(* Logix 5000 project; controller AMCI_5034_PTO_AM_Sample vendor 1 type 14 code 190 rev 37.11; software revision 37.00 *)

TASK MainTask (continuous, watchdog 500 ms) : MainProgram

MODULES
   Local : vendor 1 type 14 code 190 (5069 0, rev 37.11)
      AENTR : vendor 1 type 12 code 334 (Ethernet 192.168.1.40, rev 1.1)
         AMCI_5034_PTO_AM : vendor 10 type 100 code 34 (5034 1, rev 1.1, StandardDataDriven RPI 10 ms)
END_MODULES

TYPE AMCI_5034_PTO_AM_Input_Data :
STRUCT
   ConnectionFaulted : DINT;
   MovingCW : BOOL;
   MovingCCW : BOOL;
   InHoldState : BOOL;
   Stopped : BOOL;
   AtHome : BOOL;
   Accelerating : BOOL;
   Decelerating : BOOL;
   MoveComplete : BOOL;
   HomeInvalid : BOOL;
   InvalidProfile : BOOL;
   PositionInvalid : BOOL;
   InputError : BOOL;
   CommandError : BOOL;
   ConfigurationError : BOOL;
   ModuleOK : BOOL;
   GeneralPurposeOutputStatus : BOOL;
   Input1Active : BOOL;
   Input2Active : BOOL;
   Input3Active : BOOL;
   Input4Active : BOOL;
   bit_20_reserved : BOOL;
   bit_21_reserved : BOOL;
   bit_22_reserved : BOOL;
   EncoderFollowerMode : BOOL;
   BlendMoveRunning : BOOL;
   BlendMoveAcknowledge : BOOL;
   MinimumRegistrationProgrammed : BOOL;
   EncoderMotionDirection : BOOL;
   MultipleInputsWithSameFunction : BOOL;
   FSCExceedsNumberOfDataBits : BOOL;
   AbsoluteEncoderSetupError : BOOL;
   bit_31_reserved : BOOL;
   CurrentPosition : DINT;
   EncoderPosition : DINT;
   CapturedPosition : DINT;
END_STRUCT
END_TYPE

TYPE AMCI_5034_PTO_AM_Output_Data :
STRUCT
   Command_Word : DINT;
   TargetPosition : DINT;
   TargetVelocity : UDINT;
   Acceleration : DINT;
   Deceleration : DINT;
END_STRUCT
END_TYPE

ADD_ON_INSTRUCTION AMCI_5034_PTO_AM_Encoder_Follower   (* revision 1.0, vendor AMCI, ExecuteEnableInFalse *)
// AMCI Encoder Follower
// Revision note:
// 10/01/2025  Initial release of AOI.
// Help:
// AXIS INPUT DATA:  Input data from the AMCI 5034-PTO-AM.   Uses the AMCI_5034_PTO_Input_Data User Defined Data Type.
// AXIS OUTPUT DATA; Output data from the AOI to the AMCI 5034-PTO-AM.    Uses the AMCI_5034_PTO_Output_Data User Defined Data Type.
// DIRECTION_0_POSITIVECW_1_NEGATIVECCW: 0 to have the output steps be in the same direction as the encoder pulses.   1 to have the output steps be in the opposite direction from the encoder pulses.
// MULTIPLIER: The incoming encoder data is muliplied by this number.
// DIVISOR: The incomming encoder data is divided by this number.
// ACCELERATION: Acceleration Rate in units of steps / sec / ms.  Can be zero with the encoder follower.
// DECELERATION:  Deceleration Rate in units of steps / sec / ms.  Can be zero with the encoder follower.
// EN (Enable) Set when rung is true, Reset when rung is false
// DN (Done) Set when command is sent to the motion device.  Reset when the rung is false.
// ER (Error) Set when a command or input error failed to clear.  Reset when the rung is false.
// IP (In Process) Set when motion is occurring.   Reset when motion stops or the rung goes false.
VAR_IN_OUT
   Axis_Input_Data : AMCI_5034_PTO_AM_Input_Data; {required}
   Axis_Output_Data : AMCI_5034_PTO_AM_Output_Data; {required}
END_VAR
VAR_INPUT
   Direction_0_PositiveCW_1_NegativeCCW : BOOL; {required}
   Multiplier : DINT; {required}
   Divisor : DINT; {required}
   Acceleration : DINT; {required}
   Deceleration : DINT; {required}
END_VAR
VAR_OUTPUT
   EN : BOOL; {visible}   // set when rung with AOI is true
   DN : BOOL; {access Read Only, visible}   // set when move was succesfully initiated
   ER : BOOL; {visible}
   IP : BOOL; {visible}   // set when motion occurring
END_VAR
VAR
   command_data_block : DINT[5];
        [0]   // Command Word
        [1]   // Target Positon
        [2]   // Programmed Speed
        [3]   // Acceleration
        [4]   // Deceleration
   motion_occurring : BOOL; {access None}
   Internal_Enable : BOOL; {access None}   // set when driver ready to receive motion command
END_VAR

ROUTINE EnableInFalse   (* ladder *)
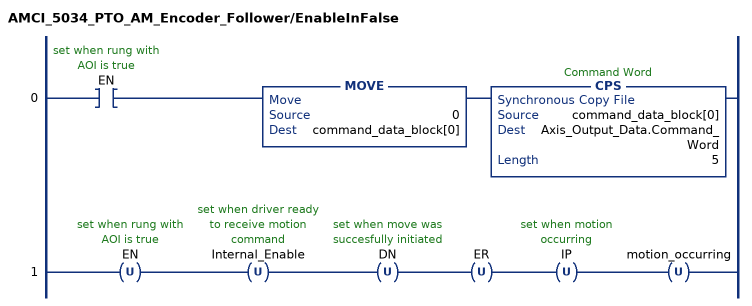
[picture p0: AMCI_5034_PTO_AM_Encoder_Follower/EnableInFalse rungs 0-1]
   0: XIC(EN)MOVE(0,command_data_block[0])CPS(command_data_block[0],Axis_Output_Data.Command_Word,5);
   1: OTU(EN)OTU(Internal_Enable)OTU(DN)OTU(ER)OTU(IP)OTU(motion_occurring);
END_ROUTINE

ROUTINE Logic   (* ladder *)
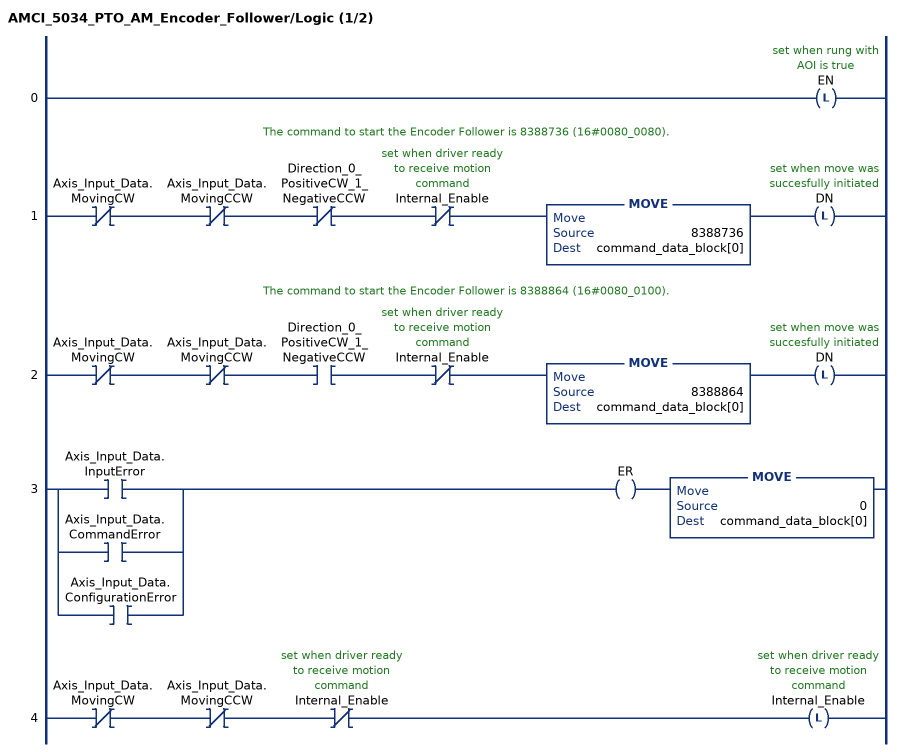
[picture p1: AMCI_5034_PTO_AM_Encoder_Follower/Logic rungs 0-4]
   0: OTL(EN);
   // The command to start the Encoder Follower is 8388736 (16#0080_0080).
   1: XIO(Axis_Input_Data.MovingCW)XIO(Axis_Input_Data.MovingCCW)XIO(Direction_0_PositiveCW_1_NegativeCCW)XIO(Internal_Enable)MOVE(8388736,command_data_block[0])OTL(DN);
   // The command to start the Encoder Follower is 8388864 (16#0080_0100).
   2: XIO(Axis_Input_Data.MovingCW)XIO(Axis_Input_Data.MovingCCW)XIC(Direction_0_PositiveCW_1_NegativeCCW)XIO(Internal_Enable)MOVE(8388864,command_data_block[0])OTL(DN);
   3: [XIC(Axis_Input_Data.InputError) ,XIC(Axis_Input_Data.CommandError) ,XIC(Axis_Input_Data.ConfigurationError) ]OTE(ER)MOVE(0,command_data_block[0]);
   4: XIO(Axis_Input_Data.MovingCW)XIO(Axis_Input_Data.MovingCCW)XIO(Internal_Enable)OTL(Internal_Enable);
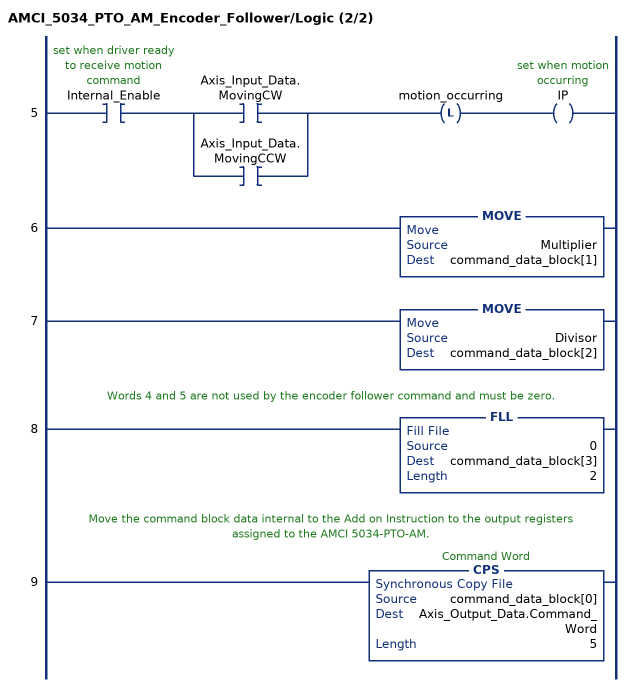
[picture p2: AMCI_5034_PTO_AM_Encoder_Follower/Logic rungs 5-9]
   5: XIC(Internal_Enable)[XIC(Axis_Input_Data.MovingCW) ,XIC(Axis_Input_Data.MovingCCW) ]OTL(motion_occurring)OTE(IP);
   6: MOVE(Multiplier,command_data_block[1]);
   7: MOVE(Divisor,command_data_block[2]);
   // Words 4 and 5 are not used by the encoder follower command and must be zero.
   8: FLL(0,command_data_block[3],2);
   // Move the command block data internal to the Add on Instruction to the output registers assigned to the AMCI 5034-PTO-AM.
   9: CPS(command_data_block[0],Axis_Output_Data.Command_Word,5);
END_ROUTINE
END_ADD_ON_INSTRUCTION

ADD_ON_INSTRUCTION AMCI_5034_PTO_AM_Hold   (* revision 1.0, vendor AMCI, ExecuteEnableInFalse *)
// AMCI Hold
// Revision note:
// 10/01/2025 Initial Release
// Help:
// AXIS INPUT DATA:  Input data from the AMCI 5034-PTO-AM.   Uses the AMCI_5034_PTO_Input_Data User Defined Data Type.
// AXIS OUTPUT DATA; Output data from the AOI to the AMCI 5034-PTO-AM.    Uses the AMCI_5034_PTO_Output_Data User Defined Data Type.
// EN (Enable) Set when rung is true, Reset when rung is false
// DN (Done) Set when command is sent to the motion device.  Reset when the rung is false.
// ER (Error) Set when a command or input error failed to clear.  Reset when the rung is false.
VAR_IN_OUT
   Axis_Input_Data : AMCI_5034_PTO_AM_Input_Data; {required}
   Axis_Output_Data : AMCI_5034_PTO_AM_Output_Data; {required}
END_VAR
VAR_OUTPUT
   EN : BOOL; {visible}   // set when rung with AOI is true
   DN : BOOL; {access Read Only, visible}   // set when reset error command sent to motion axis
   ER : BOOL; {access Read Only, visible}   // set when reset error command did not clear the error
END_VAR
VAR
   command_data_block : DINT[5];
        [0]   // Command Bits MSW
        [1]   // Command Bits LSW
        [2]   // Upper Target Position
        [3]   // Lower Target Position
        [4]   // Upper Programmed Speed
END_VAR

ROUTINE EnableInFalse   (* ladder *)
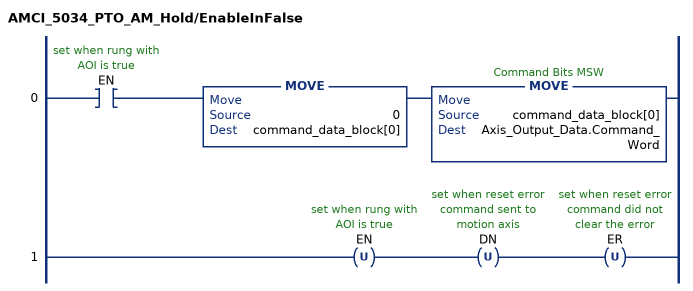
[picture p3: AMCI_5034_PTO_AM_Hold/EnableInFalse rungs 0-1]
   0: XIC(EN)MOVE(0,command_data_block[0])MOVE(command_data_block[0],Axis_Output_Data.Command_Word);
   1: OTU(EN)OTU(DN)OTU(ER);
END_ROUTINE

ROUTINE Logic   (* ladder *)
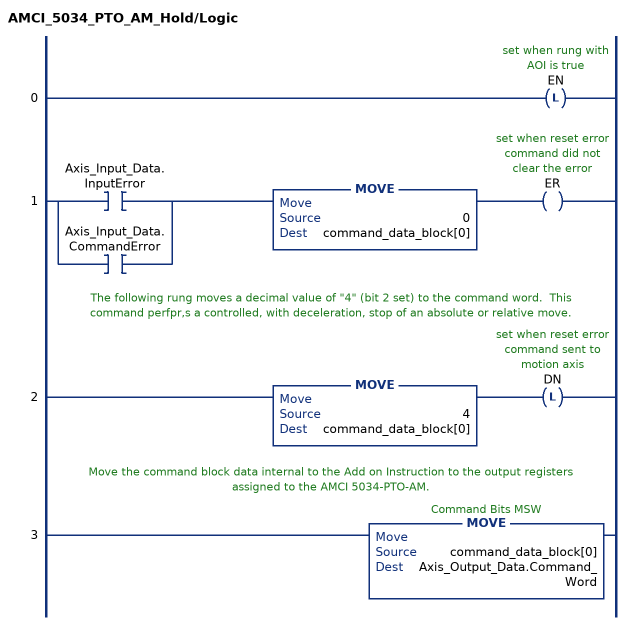
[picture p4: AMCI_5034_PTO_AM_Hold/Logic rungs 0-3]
   0: OTL(EN);
   1: [XIC(Axis_Input_Data.InputError) ,XIC(Axis_Input_Data.CommandError) ]MOVE(0,command_data_block[0])OTE(ER);
   // The following rung moves a decimal value of "4" (bit 2 set) to the command word.  This command perfpr,s a controlled, with deceleration, stop of an absolute or relative move.
   2: MOVE(4,command_data_block[0])OTL(DN);
   // Move the command block data internal to the Add on Instruction to the output registers assigned to the AMCI 5034-PTO-AM.
   3: MOVE(command_data_block[0],Axis_Output_Data.Command_Word);
END_ROUTINE
END_ADD_ON_INSTRUCTION

ADD_ON_INSTRUCTION AMCI_5034_PTO_AM_Immediate_Stop   (* revision 1.0, vendor AMCI, ExecuteEnableInFalse *)
// AMCI Immediate Stop
// Revision note:
// 10/01/2025 Initial Release
// Help:
// AXIS INPUT DATA:  Input data from the AMCI 5034-PTO-AM.   Uses the AMCI_5034_PTO_Input_Data User Defined Data Type.
// AXIS OUTPUT DATA; Output data from the AOI to the AMCI 5034-PTO-AM.    Uses the AMCI_5034_PTO_Output_Data User Defined Data Type.
// EN (Enable) Set when rung is true, Reset when rung is false
// DN (Done) Set when command is sent to the motion device.  Reset when the rung is false.
// ER (Error) Set when a command or input error failed to clear.  Reset when the rung is false.
VAR_IN_OUT
   Axis_Input_Data : AMCI_5034_PTO_AM_Input_Data; {required}
   Axis_Output_Data : AMCI_5034_PTO_AM_Output_Data; {required}
END_VAR
VAR_OUTPUT
   EN : BOOL; {visible}   // set when rung with AOI is true
   DN : BOOL; {access Read Only, visible}   // set when reset error command sent to motion axis
   ER : BOOL; {access Read Only, visible}   // set when reset error command did not clear the error
END_VAR
VAR
   command_data_block : DINT[5];
        [0]   // Command Bits MSW
        [1]   // Command Bits LSW
        [2]   // Upper Target Position
        [3]   // Lower Target Position
        [4]   // Upper Programmed Speed
END_VAR

ROUTINE EnableInFalse   (* ladder *)
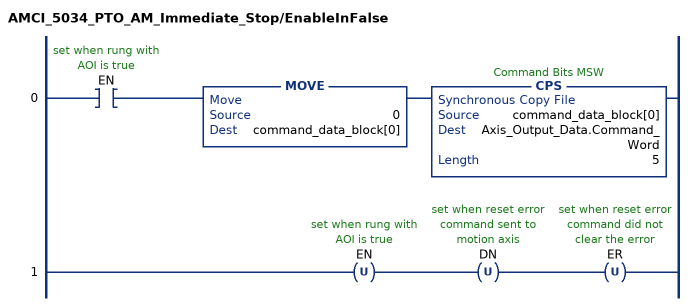
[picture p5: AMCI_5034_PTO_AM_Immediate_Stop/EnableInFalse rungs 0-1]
   0: XIC(EN)MOVE(0,command_data_block[0])CPS(command_data_block[0],Axis_Output_Data.Command_Word,5);
   1: OTU(EN)OTU(DN)OTU(ER);
END_ROUTINE

ROUTINE Logic   (* ladder *)
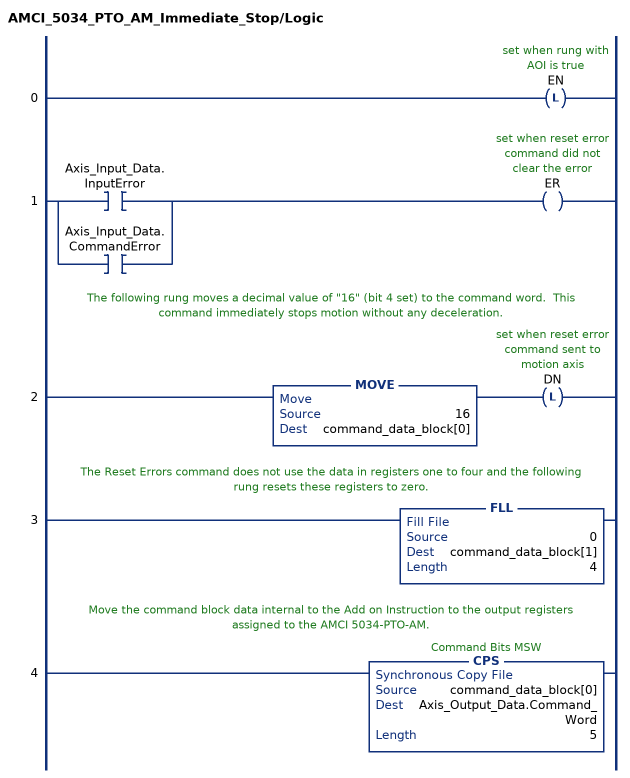
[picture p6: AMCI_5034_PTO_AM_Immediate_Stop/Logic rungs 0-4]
   0: OTL(EN);
   1: [XIC(Axis_Input_Data.InputError) ,XIC(Axis_Input_Data.CommandError) ]OTE(ER);
   // The following rung moves a decimal value of "16" (bit 4 set) to the command word.  This command immediately stops motion without any deceleration.
   2: MOVE(16,command_data_block[0])OTL(DN);
   // The Reset Errors command does not use the data in registers one to four and the following rung resets these registers to zero.
   3: FLL(0,command_data_block[1],4);
   // Move the command block data internal to the Add on Instruction to the output registers assigned to the AMCI 5034-PTO-AM.
   4: CPS(command_data_block[0],Axis_Output_Data.Command_Word,5);
END_ROUTINE
END_ADD_ON_INSTRUCTION

ADD_ON_INSTRUCTION AMCI_5034_PTO_AM_MAFR   (* revision 1.0, vendor AMCI, ExecuteEnableInFalse *)
// AMCI Reset Errors
// Revision note:
// 10/01/2025 Initial Release
// Help:
// MOTION AXIS FAULT RESET:   Resets Command and Input Errors.  It will also reset the Move Complete Status Bit.
// AXIS INPUT DATA:  Input data from the AMCI 5034-PTO-AM.   Uses the AMCI_5034_PTO_Input_Data User Defined Data Type.
// AXIS OUTPUT DATA; Output data from the AOI to the AMCI 5034-PTO-AM.    Uses the AMCI_5034_PTO_Output_Data User Defined Data Type.
// EN (Enable) Set when rung is true, Reset when rung is false
// DN (Done) Set when command is sent to the motion device.  Reset when the rung is false.
// ER (Error) Set when a command or input error failed to clear.  Reset when the rung is false.
VAR_IN_OUT
   Axis_Input_Data : AMCI_5034_PTO_AM_Input_Data; {required}
   Axis_Output_Data : AMCI_5034_PTO_AM_Output_Data; {required}
END_VAR
VAR_OUTPUT
   EN : BOOL; {visible}   // set when rung with AOI is true
   DN : BOOL; {access Read Only, visible}   // set when reset error command sent to motion axis
   ER : BOOL; {access Read Only, visible}   // set when reset error command did not clear the error
END_VAR
VAR
   command_data_block : DINT[5];
        [0]   // Command Bits MSW
        [1]   // Command Bits LSW
        [2]   // Upper Target Position
        [3]   // Lower Target Position
        [4]   // Upper Programmed Speed
END_VAR

ROUTINE EnableInFalse   (* ladder *)
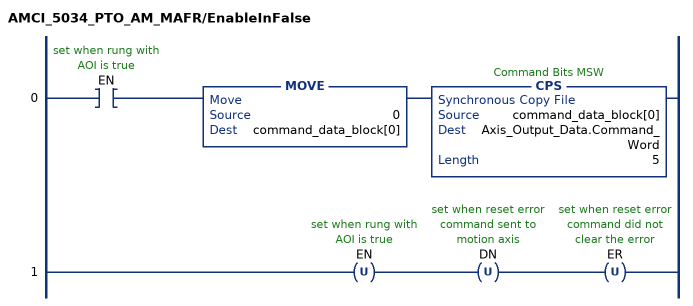
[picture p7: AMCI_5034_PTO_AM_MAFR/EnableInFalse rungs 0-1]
   0: XIC(EN)MOVE(0,command_data_block[0])CPS(command_data_block[0],Axis_Output_Data.Command_Word,5);
   1: OTU(EN)OTU(DN)OTU(ER);
END_ROUTINE

ROUTINE Logic   (* ladder *)
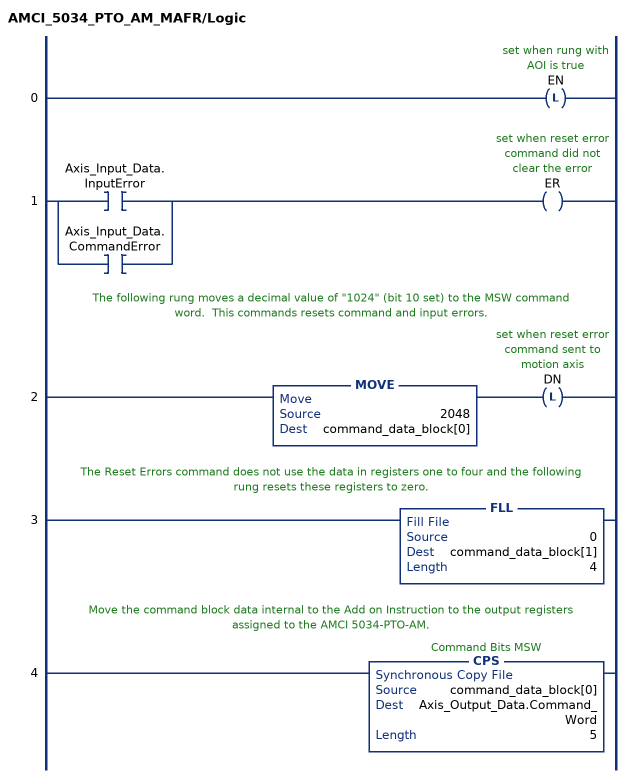
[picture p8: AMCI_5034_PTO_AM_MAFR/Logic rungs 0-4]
   0: OTL(EN);
   1: [XIC(Axis_Input_Data.InputError) ,XIC(Axis_Input_Data.CommandError) ]OTE(ER);
   // The following rung moves a decimal value of "1024" (bit 10 set) to the MSW command word.  This commands resets command and input errors.
   2: MOVE(2048,command_data_block[0])OTL(DN);
   // The Reset Errors command does not use the data in registers one to four and the following rung resets these registers to zero.
   3: FLL(0,command_data_block[1],4);
   // Move the command block data internal to the Add on Instruction to the output registers assigned to the AMCI 5034-PTO-AM.
   4: CPS(command_data_block[0],Axis_Output_Data.Command_Word,5);
END_ROUTINE
END_ADD_ON_INSTRUCTION

ADD_ON_INSTRUCTION AMCI_5034_PTO_AM_MAH   (* revision 1.0, vendor AMCI, ExecuteEnableInFalse *)
// AMCI Home
// Revision note:
// 10/01/2025 V1.0  Initial release of AOI
// Help:
// MOTION AXIS HOME:   Performs CW or CCW Home Moves to a Home Input.
// AXIS INPUT DATA:  Input data from the AMCI 5034-PTO-AM.   Uses the AMCI_5034_PTO_Input_Data User Defined Data Type.
// AXIS OUTPUT DATA; Output data from the AOI to the AMCI 5034-PTO-AM.    Uses the AMCI_5034_PTO_Output_Data User Defined Data Type.
// DIRECTION: 0 for Positive CW Home or  1 for Negative CCW Home
// TARGET VELOCITY: Speed of move in units of steps / sec
// ACCELERATION: Acceleration Rate in units of steps / sec / ms
// DECELERATION:  Deceleration Rate in units of steps / sec / ms
// EN (Enable) Set when rung is true, Reset when rung is false
// DN (Done) Set when command is sent to the motion device.  Reset when the rung is false.
// ER (Error) Set when a command or input error failed to clear.  Reset when the rung is false.
// IP (In Process) Set when motion is occurring.   Reset when motion stops or the rung goes false.
// PC (Process Complete) Set when the At Home Status bit is set.   Reset the next time the rung with the AOI                                      goes from false to true.
VAR_IN_OUT
   Axis_Input_Data : AMCI_5034_PTO_AM_Input_Data; {required}
   Axis_Output_Data : AMCI_5034_PTO_AM_Output_Data; {required}
END_VAR
VAR_INPUT
   Direction_0_PositiveCW_1_NegativeCCW : BOOL; {required}   // 0=home CW 1=home CCW
   TargetVelocity : DINT; {required}
   Acceleration : DINT; {required}
   Deceleration : DINT; {required}
END_VAR
VAR_OUTPUT
   EN : BOOL; {visible}   // set when rung with AOI is true
   DN : BOOL; {access Read Only, visible}   // set when move was succesfully initiated
   ER : BOOL; {visible}   // input, command, or configuration error
   IP : BOOL; {visible}   // set when motion occurring
   PC : BOOL; {visible}   // set when process complete
END_VAR
VAR
   command_data_block : DINT[5];
        [0]   // Command Bits MSW
        [1]   // Targert Position
        [2]   // Programmed Speed
        [3]   // Lower Target Position
        [4]   // Upper Programmed Speed
   motion_occurring : BOOL; {access None}
   Internal_Enable : BOOL; {access None}   // set when driver ready to receive motion command
END_VAR

ROUTINE EnableInFalse   (* ladder *)
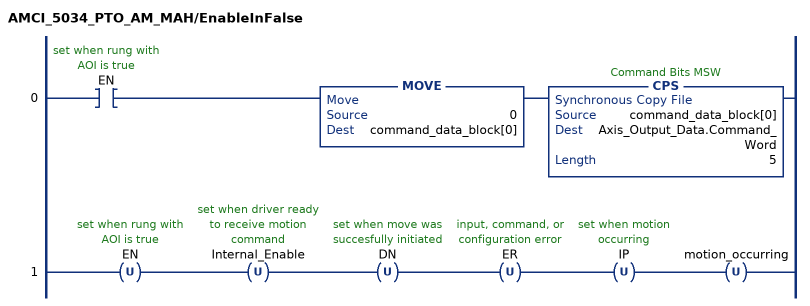
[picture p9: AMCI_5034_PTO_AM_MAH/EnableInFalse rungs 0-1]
   0: XIC(EN)MOVE(0,command_data_block[0])CPS(command_data_block[0],Axis_Output_Data.Command_Word,5);
   1: OTU(EN)OTU(Internal_Enable)OTU(DN)OTU(ER)OTU(IP)OTU(motion_occurring);
END_ROUTINE

ROUTINE Logic   (* ladder *)
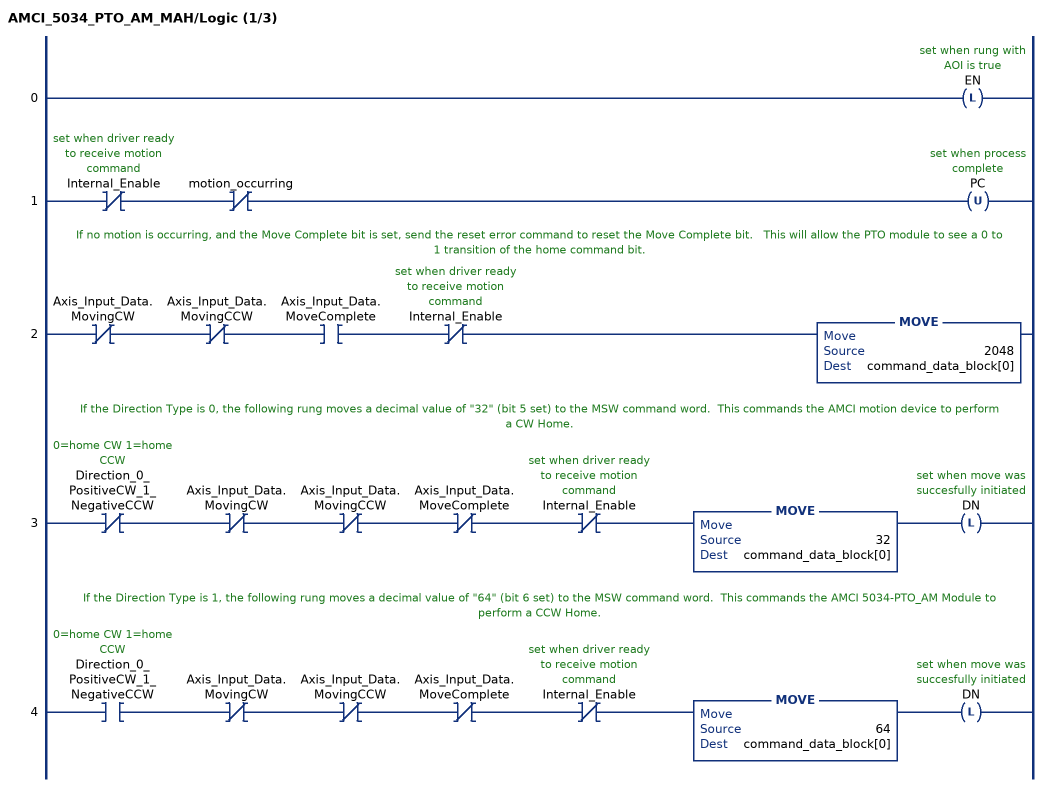
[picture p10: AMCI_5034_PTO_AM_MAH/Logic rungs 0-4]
   0: OTL(EN);
   1: XIO(Internal_Enable)XIO(motion_occurring)OTU(PC);
   // If no motion is occurring, and the Move Complete bit is set, send the reset error command to reset the Move Complete bit.   This will allow the PTO module to see a 0 to 1 transition of the home command bit.
   2: XIO(Axis_Input_Data.MovingCW)XIO(Axis_Input_Data.MovingCCW)XIC(Axis_Input_Data.MoveComplete)XIO(Internal_Enable)MOVE(2048,command_data_block[0]);
   // If the Direction Type is 0, the following rung moves a decimal value of "32" (bit 5 set) to the MSW command word.  This commands the AMCI motion device to perform a CW Home.
   3: XIO(Direction_0_PositiveCW_1_NegativeCCW)XIO(Axis_Input_Data.MovingCW)XIO(Axis_Input_Data.MovingCCW)XIO(Axis_Input_Data.MoveComplete)XIO(Internal_Enable)MOVE(32,command_data_block[0])OTL(DN);
   // If the Direction Type is 1, the following rung moves a decimal value of "64" (bit 6 set) to the MSW command word.  This commands the AMCI 5034-PTO_AM Module to perform a CCW Home.
   4: XIC(Direction_0_PositiveCW_1_NegativeCCW)XIO(Axis_Input_Data.MovingCW)XIO(Axis_Input_Data.MovingCCW)XIO(Axis_Input_Data.MoveComplete)XIO(Internal_Enable)MOVE(64,command_data_block[0])OTL(DN);
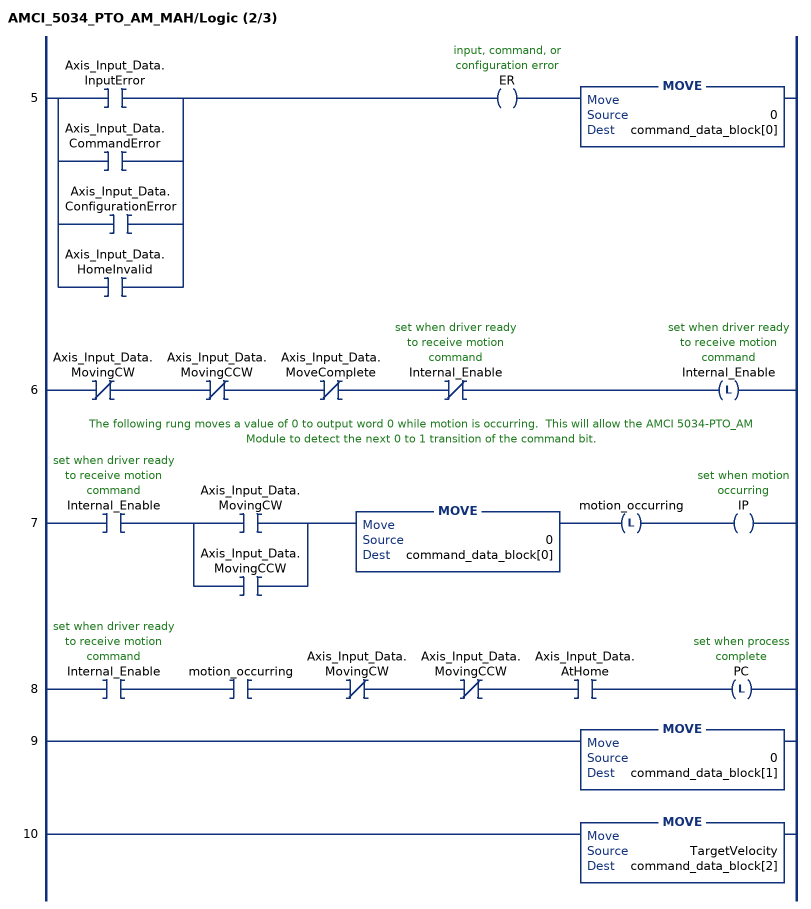
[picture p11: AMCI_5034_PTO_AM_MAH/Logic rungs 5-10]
   5: [XIC(Axis_Input_Data.InputError) ,XIC(Axis_Input_Data.CommandError) ,XIC(Axis_Input_Data.ConfigurationError) ,XIC(Axis_Input_Data.HomeInvalid) ]OTE(ER)MOVE(0,command_data_block[0]);
   6: XIO(Axis_Input_Data.MovingCW)XIO(Axis_Input_Data.MovingCCW)XIO(Axis_Input_Data.MoveComplete)XIO(Internal_Enable)OTL(Internal_Enable);
   // The following rung moves a value of 0 to output word 0 while motion is occurring.  This will allow the AMCI 5034-PTO_AM Module to detect the next 0 to 1 transition of the command bit.
   7: XIC(Internal_Enable)[XIC(Axis_Input_Data.MovingCW) ,XIC(Axis_Input_Data.MovingCCW) ]MOVE(0,command_data_block[0])OTL(motion_occurring)OTE(IP);
   8: XIC(Internal_Enable)XIC(motion_occurring)XIO(Axis_Input_Data.MovingCW)XIO(Axis_Input_Data.MovingCCW)XIC(Axis_Input_Data.AtHome)OTL(PC);
   9: MOVE(0,command_data_block[1]);
   10: MOVE(TargetVelocity,command_data_block[2]);
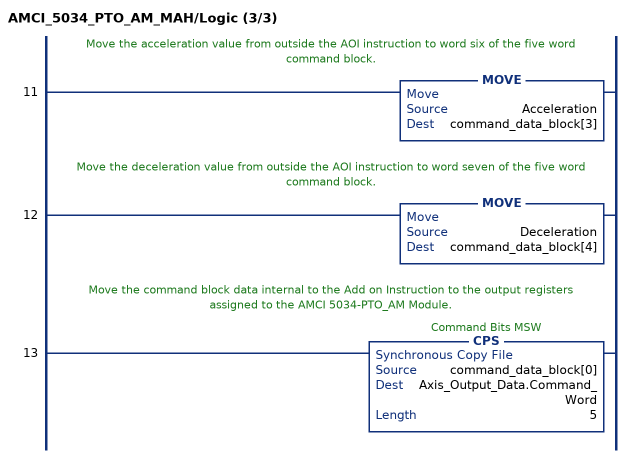
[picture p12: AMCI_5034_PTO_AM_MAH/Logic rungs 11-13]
   // Move the acceleration value from outside the AOI instruction to word six of the five word command block.
   11: MOVE(Acceleration,command_data_block[3]);
   // Move the deceleration value from outside the AOI instruction to word seven of the five word command block.
   12: MOVE(Deceleration,command_data_block[4]);
   // Move the command block data internal to the Add on Instruction to the output registers assigned to the AMCI 5034-PTO_AM Module.
   13: CPS(command_data_block[0],Axis_Output_Data.Command_Word,5);
END_ROUTINE
END_ADD_ON_INSTRUCTION

ADD_ON_INSTRUCTION AMCI_5034_PTO_AM_MAJ   (* revision 1.0, vendor AMCI, ExecuteEnableInFalse *)
// AMCI Jog
// Revision note:
// 10/01/2025  Initial release of AOI.  Making the rung false will NOT STOP THE JOG.
// Help:
// Performs Positive CW or Negative CCW Jog Moves
// AXIS INPUT DATA:  Input data from the AMCI 5034-PTO-AM.   Uses the AMCI_5034_PTO_Input_Data User Defined Data Type.
// AXIS OUTPUT DATA; Output data from the AOI to the AMCI 5034-PTO-AM.    Uses the AMCI_5034_PTO_Output_Data User Defined Data Type.
// DIRECTION: 0 for Positive CW Jog or 1 for Negative CCW Jog
// TARGETVELOCITY: Speed of move in units of steps / sec
// ACCELERATION: Acceleration Rate in units of steps / sec / ms
// DECELERATION:  Deceleration Rate in units of steps / sec / ms
// EN (Enable) Set when rung is true, Reset when rung is false
// DN (Done) Set when command is sent to the motion device.  Reset when the rung is false.
// ER (Error) Set when a command or input error failed to clear.  Reset when the rung is false.
// IP (In Process) Set when motion is occurring.   Reset when motion stops or the rung goes false.
VAR_IN_OUT
   Axis_Input_Data : AMCI_5034_PTO_AM_Input_Data; {required}
   Axis_Output_Data : AMCI_5034_PTO_AM_Output_Data; {required}
END_VAR
VAR_INPUT
   Direction_0_PositiveCW_1_NegativeCCW : BOOL; {required}   // 0=jog CW 1=jog CCW
   _0_normal_1_S_Curve_Acceleration : BOOL;
   _0_Triangular_1_Trapezoidal_S_Curve : BOOL;
   TargetVelocity : DINT; {required}
   Acceleration : DINT; {required}
   Deceleration : INT; {required}
END_VAR
VAR_OUTPUT
   EN : BOOL; {visible}   // set when rung with AOI is true
   DN : BOOL; {access Read Only, visible}   // set when move was succesfully initiated
   ER : BOOL; {visible}
   IP : BOOL; {visible}   // set when motion occurring
END_VAR
VAR
   command_data_block : DINT[5];
        [0]   // Command Word
        [1]   // Target Positon
        [2]   // Programmed Speed
        [3]   // Acceleration
        [4]   // Deceleration
   motion_occurring : BOOL; {access None}
   Internal_Enable : BOOL; {access None}   // set when driver ready to receive motion command
END_VAR

ROUTINE EnableInFalse   (* ladder *)
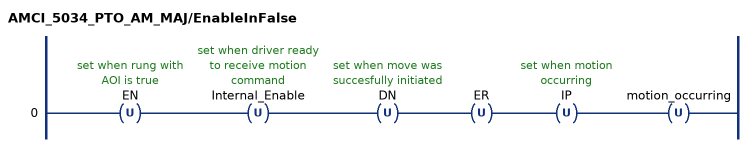
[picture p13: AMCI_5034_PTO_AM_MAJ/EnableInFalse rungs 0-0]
   0: OTU(EN)OTU(Internal_Enable)OTU(DN)OTU(ER)OTU(IP)OTU(motion_occurring);
END_ROUTINE

ROUTINE Logic   (* ladder *)
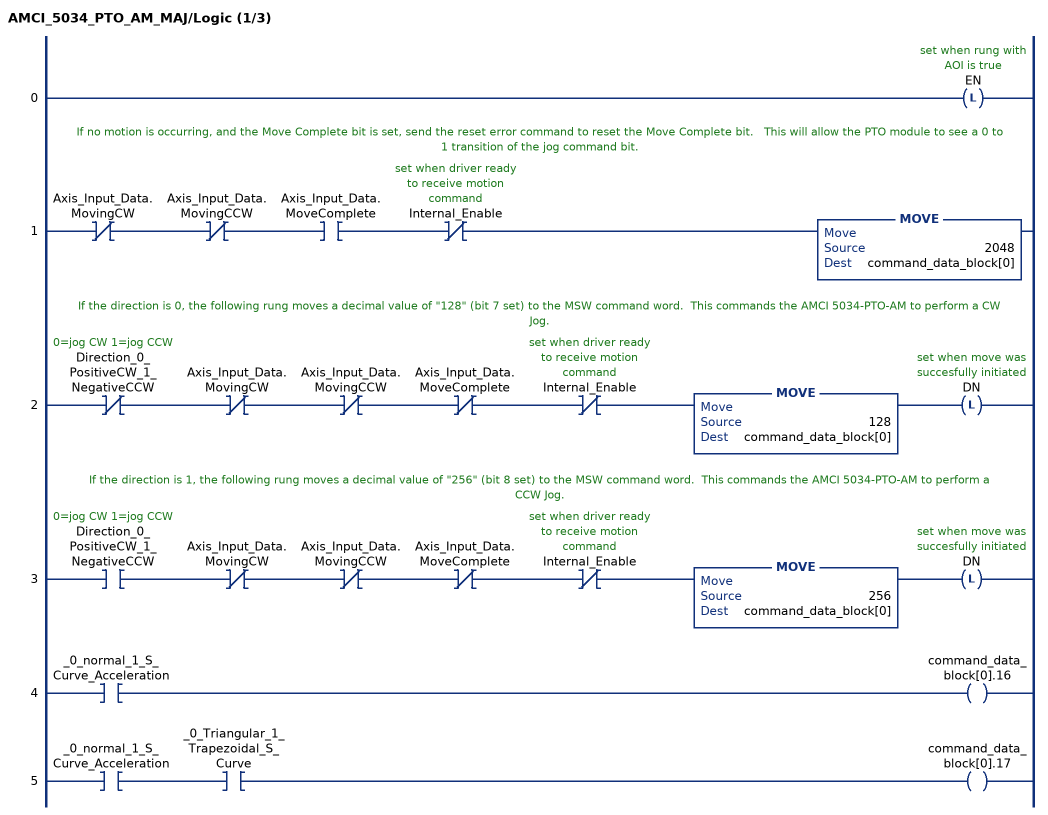
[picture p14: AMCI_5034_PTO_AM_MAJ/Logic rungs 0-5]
   0: OTL(EN);
   // If no motion is occurring, and the Move Complete bit is set, send the reset error command to reset the Move Complete bit.   This will allow the PTO module to see a 0 to 1 transition of the jog command bit.
   1: XIO(Axis_Input_Data.MovingCW)XIO(Axis_Input_Data.MovingCCW)XIC(Axis_Input_Data.MoveComplete)XIO(Internal_Enable)MOVE(2048,command_data_block[0]);
   // If the direction is 0, the following rung moves a decimal value of "128" (bit 7 set) to the MSW command word.  This commands the AMCI 5034-PTO-AM to perform a CW Jog.
   2: XIO(Direction_0_PositiveCW_1_NegativeCCW)XIO(Axis_Input_Data.MovingCW)XIO(Axis_Input_Data.MovingCCW)XIO(Axis_Input_Data.MoveComplete)XIO(Internal_Enable)MOVE(128,command_data_block[0])OTL(DN);
   // If the direction is 1, the following rung moves a decimal value of "256" (bit 8 set) to the MSW command word.  This commands the AMCI 5034-PTO-AM to perform a CCW Jog.
   3: XIC(Direction_0_PositiveCW_1_NegativeCCW)XIO(Axis_Input_Data.MovingCW)XIO(Axis_Input_Data.MovingCCW)XIO(Axis_Input_Data.MoveComplete)XIO(Internal_Enable)MOVE(256,command_data_block[0])OTL(DN);
   4: XIC(_0_normal_1_S_Curve_Acceleration)OTE(command_data_block[0].16);
   5: XIC(_0_normal_1_S_Curve_Acceleration)XIC(_0_Triangular_1_Trapezoidal_S_Curve)OTE(command_data_block[0].17);
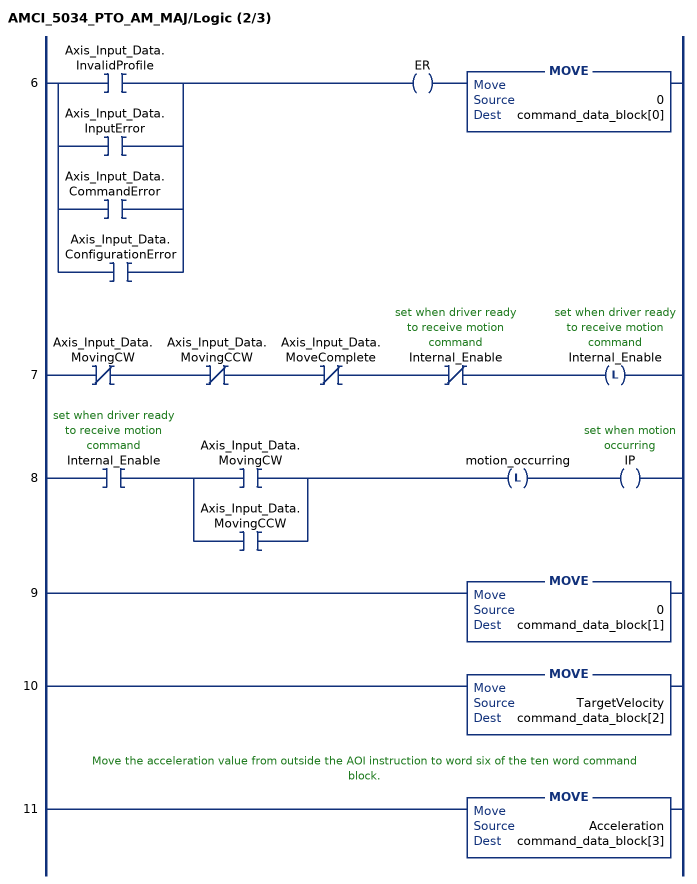
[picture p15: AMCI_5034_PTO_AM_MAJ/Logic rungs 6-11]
   6: [XIC(Axis_Input_Data.InvalidProfile) ,XIC(Axis_Input_Data.InputError) ,XIC(Axis_Input_Data.CommandError) ,XIC(Axis_Input_Data.ConfigurationError) ]OTE(ER)MOVE(0,command_data_block[0]);
   7: XIO(Axis_Input_Data.MovingCW)XIO(Axis_Input_Data.MovingCCW)XIO(Axis_Input_Data.MoveComplete)XIO(Internal_Enable)OTL(Internal_Enable);
   8: XIC(Internal_Enable)[XIC(Axis_Input_Data.MovingCW) ,XIC(Axis_Input_Data.MovingCCW) ]OTL(motion_occurring)OTE(IP);
   9: MOVE(0,command_data_block[1]);
   10: MOVE(TargetVelocity,command_data_block[2]);
   // Move the acceleration value from outside the AOI instruction to word six of the ten word command block.
   11: MOVE(Acceleration,command_data_block[3]);
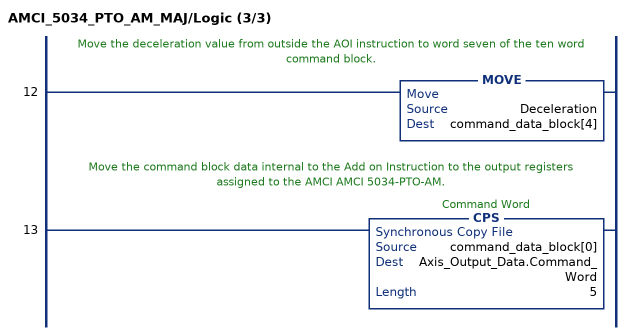
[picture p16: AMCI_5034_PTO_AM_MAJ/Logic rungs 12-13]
   // Move the deceleration value from outside the AOI instruction to word seven of the ten word command block.
   12: MOVE(Deceleration,command_data_block[4]);
   // Move the command block data internal to the Add on Instruction to the output registers assigned to the AMCI AMCI 5034-PTO-AM.
   13: CPS(command_data_block[0],Axis_Output_Data.Command_Word,5);
END_ROUTINE
END_ADD_ON_INSTRUCTION

ADD_ON_INSTRUCTION AMCI_5034_PTO_AM_MAM   (* revision 1.0, vendor AMCI, ExecuteEnableInFalse *)
// Absolute and Relative Moves
// Revision note:
// V1.0 10/01/2025 Initial release of AOI
// Help:
// MOTION AXIS MOVE: Performs Absolute or Relative Moves
// AXIS INPUT DATA:  Input data from the AMCI 5034-PTO-AM.   Uses the AMCI_5034_PTO_Input_Data User Defined Data Type.
// AXIS OUTPUT DATA; Output data from the AOI to the AMCI 5034-PTO-AM.    Uses the AMCI_5034_PTO_Output_Data User Defined Data Type.
// MOVE TYPE: 0 = Absolute Move, 1 = Relative Move
// TARGETPOSITION: Target Position of the Absolute Move or the distance to move of a Relative                                             Move.
// TARGETVELOCITY: Speed of move in units of steps / sec
// ACCELERATION: Acceleration Rate in units of steps / sec / ms
// DECELERATION:  Deceleration Rate in units of steps / sec / ms
// EN (Enable) Set when rung is true, Reset when rung is false
// DN (Done) Set when command is sent to the motion device.  Reset when the rung is false.
// ER (Error) Set when a command or input error failed to clear.  Reset when the rung is false.
// IP (In Process) Set when motion is occurring.   Reset when motion stops or the rung goes false.
// PC (Process Complete) Set when the move is complete.  Reset the next time the rung with the AOI transitions                                       from False to True.
VAR_IN_OUT
   Axis_Input_Data : AMCI_5034_PTO_AM_Input_Data; {required}
   Axis_Output_Data : AMCI_5034_PTO_AM_Output_Data; {required}
END_VAR
VAR_INPUT
   Move_type_0_Absolute_1_Relative : BOOL; {required}   // 0=absolute 1=relative
   _0_normal_1_S_Curve_Acceleration : BOOL;
   _0_Triangular_1_Trapezoidal_S_Curve : BOOL;
   TargetPosition : DINT; {required}
   TargetVelocity : DINT; {required}
   Acceleration : DINT; {required}
   Deceleration : DINT; {required}
END_VAR
VAR_OUTPUT
   EN : BOOL; {visible}   // set when rung with AOI is true
   DN : BOOL; {access Read Only, visible}   // set when move was succesfully initiated
   ER : BOOL; {visible}   // set when input error, command error, or configuration error
   IP : BOOL; {visible}   // set when motion occurring
   PC : BOOL; {visible}   // set when process complete
END_VAR
VAR
   command_data_block : DINT[5];
        [0]   // Command Word
        [1]   // Target Position
        [2]   // Programmed Speed
        [3]   // Acceleration
        [4]   // Deceleration
   motion_occurring : BOOL; {access None}
   Internal_Enable : BOOL; {access None}   // set when driver ready to receive motion command
END_VAR

ROUTINE EnableInFalse   (* ladder *)
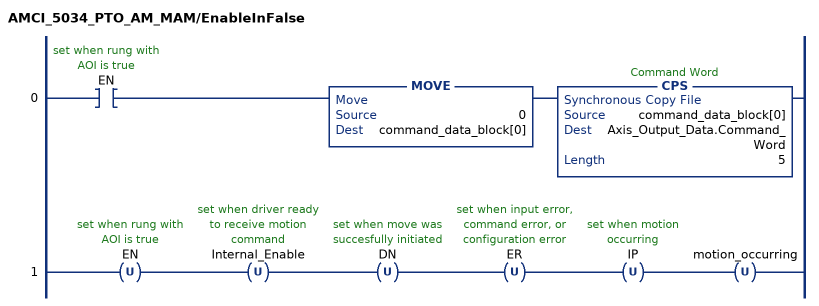
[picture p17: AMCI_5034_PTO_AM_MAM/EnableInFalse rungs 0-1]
   0: XIC(EN)MOVE(0,command_data_block[0])CPS(command_data_block[0],Axis_Output_Data.Command_Word,5);
   1: OTU(EN)OTU(Internal_Enable)OTU(DN)OTU(ER)OTU(IP)OTU(motion_occurring);
END_ROUTINE
